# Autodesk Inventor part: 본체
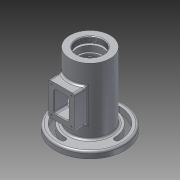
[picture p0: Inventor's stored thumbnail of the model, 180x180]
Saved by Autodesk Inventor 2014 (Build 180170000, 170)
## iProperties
Created: 2017-05
Part Number: 본체
Material: 알루미늄 6061
Document SubType Name: Modeling
Designer: Administrator
Density: 2.71 g/cm^3
Appearance: 알루미늄 - 평지
Mass: 682.498 g
Surface Area: 619.124 cm^2
Volume: 251.844 cm^3
Author: Administrator
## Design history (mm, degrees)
sketch "스케치1"
  geometry: C1 r 53 at (0, 0); 1 further point
  constraints: 1 centre point, 1 coincident
  dimensions: "d0" = 106 diameter of C1
extrude "돌출1" new body sketch "스케치1" distance "d1" = 10; taper "d2" = 0 deg
sketch "스케치2"
  geometry: C1 r 53 at (0, 0) reference; C2 r 31 at (0, 0)
  constraints: 1 centre point, 1 coincident
  dimensions: "d3" = 62 diameter of C2
extrude "돌출2" join sketch "스케치2" distance "d4" = 102; taper "d5" = 0 deg
sketch "스케치3"
  geometry: C1 r 53 at (0, 0) reference; C2 r 31 at (0, 0)
  constraints: 1 centre point, 1 coincident
  dimensions: "d6" = 62 diameter of C2
extrude "돌출3" join sketch "스케치3" distance "d7" = 3; taper "d8" = 0 deg
node "작업 평면1"
hole "구멍1" diameter "d12" = 40.376; stored, may be unused: countersink angle "d16" = 90 deg, drill point angle "d18" = 0 deg; dims "d10" = 10, "d11" = 10, "d13" = 6, "d14" = 4, "d15" = 2, "d17" = 9
sketch "스케치5"
  geometry: C1 r 20.188 at (0, 0) reference; C2 r 24 at (0, 0)
  constraints: 1 centre point, 1 coincident
  dimensions: "d19" = 48 diameter of C2
extrude "돌출4" cut sketch "스케치5" distance "d20" = 3; taper "d21" = 0 deg
sketch "스케치6"
  geometry: C1 r 24 at (0, 0) reference; C2 r 20 at (0, 0)
  constraints: 1 centre point, 1 coincident
  dimensions: "d22" = 40 diameter of C2
extrude "돌출5" cut sketch "스케치6" distance "d23" = 9; taper "d24" = 0 deg
sketch "스케치7"
  geometry: C1 r 20 at (0, 0) reference; C2 r 17.5 at (0, 0)
  constraints: 1 centre point, 1 coincident
  dimensions: "d25" = 35 diameter of C2
extrude "돌출6" cut sketch "스케치7" distance "d26" = 3.25; taper "d27" = 0 deg
sketch "스케치8"
  geometry: C1 r 17.5 at (0, 0) reference; C2 r 18.5 at (0, 0)
  constraints: 1 centre point, 1 coincident
  dimensions: "d28" = 37 diameter of C2
extrude "돌출7" cut sketch "스케치8" distance "d29" = 1.75; taper "d30" = 0 deg
sketch "스케치9"
  geometry: C1 r 18.5 at (0, 0) reference; C2 r 17.5 at (0, 0)
  constraints: 1 centre point, 1 coincident
  dimensions: "d31" = 35 diameter of C2
extrude "돌출8" cut sketch "스케치9" distance "d32" = 11; taper "d33" = 0 deg
sketch "스케치10"
  geometry: C1 r 17.5 at (0, 0) reference; C2 r 26 at (0, 0)
  constraints: 1 centre point, 1 coincident
  dimensions: "d34" = 52 diameter of C2
extrude "돌출9" cut sketch "스케치10" distance "d35" = 38; taper "d36" = 0 deg
sketch "스케치11"
  geometry: C1 r 26 at (0, 0) reference; C2 r 17.5 at (0, 0)
  constraints: 1 centre point, 1 coincident
  dimensions: "d37" = 35 diameter of C2
extrude "돌출10" cut sketch "스케치11" distance "d38" = 11; taper "d39" = 0 deg
sketch "스케치12"
  geometry: C1 r 17.5 at (0, 0) reference; C2 r 16.5 at (0, 0)
  constraints: 1 centre point, 1 coincident
  dimensions: "d40" = 33 diameter of C2
extrude "돌출11" cut sketch "스케치12" distance "d41" = 5; taper "d42" = 0 deg
sketch "스케치13"
  geometry: C1 r 16.5 at (0, 0) reference; C2 r 10 at (0, 0)
  constraints: 1 centre point, 1 coincident
  dimensions: "d43" = 20 diameter of C2
extrude "돌출12" cut sketch "스케치13" distance "d44" = 2.7; taper "d45" = 0 deg
sketch "스케치14"
  geometry: C1 r 10 at (0, 0) reference; C2 r 12.5 at (0, 0)
  constraints: 1 centre point, 1 coincident
  dimensions: "d46" = 25 diameter of C2
extrude "돌출13" cut sketch "스케치14" distance "d47" = 6.6; taper "d48" = 0 deg
sketch "스케치15"
  geometry: C1 r 12.5 at (0, 0) reference; C2 r 12.5 at (0, 0)
  constraints: 1 centre point, 1 coincident
  dimensions: "d49" = 25 diameter of C2
extrude "돌출14" cut sketch "스케치15" distance "d50" = 0.7; taper "d51" = 30 deg
node "작업 평면2"
node "작업 평면3"
sketch "스케치17"
  geometry: L1 (53, 10)-(53, 0) reference; L2 (53, 0)-(31, 0) reference; L3 (31, 0)-(31, -3) reference; L4 (31, -3)-(-31, -3) reference; L5 (-31, -3)-(-31, 0) reference; L6 (-31, 0)-(-53, 0) reference; L7 (-53, 0)-(-53, 10) reference; L8 (-53, 10)-(-31, 10) reference; L9 (-31, 10)-(-31, 112) reference; L10 (-31, 112)-(-20.188, 112) reference; L11 (-20.188, 112)-(-20.188, 103) reference; L12 (-20.188, 103)-(-24, 103) reference; L13 (-24, 103)-(-24, 100) reference; L14 (-24, 100)-(-20, 100) reference; L15 (-20, 100)-(-20, 91) reference; L16 (-20, 91)-(-17.5, 91) reference; L17 (-17.5, 91)-(-17.5, 87.75) reference; L18 (-17.5, 87.75)-(-18.5, 87.75) reference; L19 (-18.5, 87.75)-(-18.5, 86) reference; L20 (-18.5, 86)-(-17.5, 86) reference; L21 (-17.5, 86)-(-17.5, 75) reference; L22 (-17.5, 75)-(-26, 75) reference; L23 (-26, 75)-(-26, 37) reference; L24 (-26, 37)-(-17.5, 37) reference; L25 (-17.5, 37)-(-17.5, 26) reference; L26 (-17.5, 26)-(-16.5, 26) reference; L27 (-16.5, 26)-(-16.5, 21) reference; L28 (-16.5, 21)-(-10, 21) reference; L29 (-10, 21)-(-10, 18.3) reference; L30 (-10, 18.3)-(-12.5, 18.3) reference; L31 (-12.5, 18.3)-(-12.5, 11.7) reference; L32 (-12.5, 11.7)-(-12.904, 11) reference; L33 (-12.904, 11)-(12.904, 11) reference; L34 (12.904, 11)-(12.5, 11.7) reference; L35 (12.5, 11.7)-(12.5, 18.3) reference; L36 (12.5, 18.3)-(10, 18.3) reference; L37 (10, 18.3)-(10, 21) reference; L38 (10, 21)-(16.5, 21) reference; L39 (16.5, 21)-(16.5, 26) reference; L40 (16.5, 26)-(17.5, 26) reference; L41 (17.5, 26)-(17.5, 37) reference; L42 (17.5, 37)-(26, 37) reference; L43 (26, 37)-(26, 75) reference; L44 (26, 75)-(17.5, 75) reference; L45 (17.5, 75)-(17.5, 86) reference; L46 (17.5, 86)-(18.5, 86) reference; L47 (18.5, 86)-(18.5, 87.75) reference; L48 (18.5, 87.75)-(17.5, 87.75) reference; L49 (17.5, 87.75)-(17.5, 91) reference; L50 (17.5, 91)-(20, 91) reference; L51 (20, 91)-(20, 100) reference; L52 (20, 100)-(24, 100) reference; L53 (24, 100)-(24, 103) reference; L54 (24, 103)-(20.188, 103) reference; L55 (20.188, 103)-(20.188, 112) reference; L56 (20.188, 112)-(31, 112) reference; L57 (31, 112)-(31, 10) reference; L58 (31, 10)-(53, 10) reference; L59 (0, 11)-(0, -3); L60 (0, 11)-(16, 11); L61 (0, -3)-(22, -3); L62 (16, 11)-(22, -3); 1 further point
  constraints: 8 end point, 2 midpoint, 2 point on line
  dimensions: "d54" = 44 diameter of L61.end L59; "d55" = 32 diameter of L60.end L59
revolve "회전1" sketch "스케치17" stored, may be unused: angle "d56" = 90 deg
node "작업 평면4"
node "작업 평면5"
sketch "스케치19"
  geometry: L1 (-29.547, 0)-(-29.547, 10) reference; L2 (-29.547, 10)-(29.547, 10) reference; L3 (29.547, 10)-(29.547, 0) reference; L4 (29.547, 0)-(-29.547, 0) reference; L5 (31, 112)-(-31, 112) reference; L6 (20, 81)-(-20, 81); L7 (-20, 81)-(-20, 31); L8 (-20, 31)-(20, 31); L9 (20, 31)-(20, 81); L10 (20, 81)-(-20, 31); L11 (-20, 81)-(20, 31); 4 further points
  constraints: 12 end point, 4 midpoint, 2 parallel, 1 horizontal, 1 perpendicular, 1 vertical alignment
  dimensions: "d62" = 56 distance from line of L5 point (0, 56); "d63" = 50 distance of L8.end L6.start; "d64" = 40 distance of L6.start L6.end
extrude "돌출15" join sketch "스케치19" stored distance "d65" = 0.7; taper "d66" = 0 deg
sketch "스케치20"
  geometry: L1 (-20, 81)-(-20, 31) reference; L2 (-20, 31)-(20, 31) reference; L3 (20, 31)-(20, 81) reference; L4 (20, 81)-(-20, 81) reference; L5 (11, 72)-(11, 40); L6 (11, 40)-(-11, 40); L7 (-11, 40)-(-11, 72); L8 (-11, 72)-(11, 72); 3 further points
  constraints: 8 end point, 2 midpoint, 1 vertical alignment, 3 other
  dimensions: "d68" = 32 distance of L5.start L5.end; "d69" = 22 distance of L7.end L5.start (derived)
extrude "돌출16" cut sketch "스케치20" stored distance "d70" = 0.7; taper "d71" = 0 deg
hole "구멍2" diameter "d74" = 2.459; stored, may be unused: countersink angle "d78" = 90 deg, drill point angle "d80" = 118 deg; dims "d72" = 4.5, "d73" = 4.5, "d75" = 6, "d76" = 4, "d77" = 2, "d79" = 8
sketch "스케치22"
  geometry: C1 r 31 at (0, 0) reference; C2 r 53 at (0, 0) reference; A1 r 41.5 centre (0, 0) between (41.5, 0) and (0, -41.5); A2 r 37.5 centre (0, 0) between (37.5, 0) and (0, 37.5); A3 r 4 centre (41.5, 0) between (45.5, 0) and (37.5, 0); A4 r 4 centre (0, -41.5) between (0, -37.5) and (0, -45.5); A5 r 4 centre (0, 41.5) between (0, 37.5) and (0, 45.5); A6 r 4 centre (-41.5, 0) between (-45.5, 0) and (-37.5, 0); A7 r 45.5 centre (0, 0) between (0, 45.5) and (-45.5, 0); A8 r 37.5 centre (0, 0) between (0, 37.5) and (-37.5, 0); A9 r 37.5 centre (0, 0) between (0, -37.5) and (37.5, 0); A10 r 45.5 centre (0, 0) between (0, -45.5) and (45.5, 0)
  constraints: 22 point on circle, 10 centre point, 6 coincident, 2 horizontal alignment, 2 vertical alignment, 1 tangent
  dimensions: "d87" = 83 diameter of A1; "d88" = 75 diameter of A2; "d89" = 8 diameter of A3; "d90" = 8 diameter of A4; "d91" = 8 diameter of A5; "d92" = 8 diameter of A6; "d93" = 45.5 radius of A7
extrude "돌출17" cut sketch "스케치22" distance "d94" = 10; taper "d95" = 0 deg
node "작업 평면6"
sketch "스케치23"
  geometry: L1 (-16.613, 37)-(16.613, 37) reference; L2 (16.613, 37)-(16.613, 75) reference; L3 (16.613, 75)-(-16.613, 75) reference; L4 (-16.613, 75)-(-16.613, 37) reference; L5 (49.082, 10)-(49.082, 0) reference; L6 (49.082, 0)-(40.869, 0) reference; L7 (40.869, 0)-(40.869, 10) reference; L8 (40.869, 10)-(49.082, 10) reference; L9 (-49.082, 0)-(-49.082, 10) reference; L10 (-49.082, 10)-(-23.685, 10) reference; L11 (-23.685, 10)-(-23.685, 112) reference; L12 (-23.685, 112)-(-2.749, 112) reference; L13 (-2.749, 112)-(-2.749, 103) reference; L14 (-2.749, 103)-(-13.266, 103) reference; L15 (-13.266, 103)-(-13.266, 100) reference; L16 (-13.266, 100)-(0, 100) reference; L17 (0, 91)-(0, 100) reference; L18 (-23.685, 0)-(-49.082, 0) reference; L19 (-23.685, -3)-(-23.685, 0) reference; L20 (-9.165, -3)-(-23.685, -3) reference; L21 (23.685, -3)-(9.165, -3) reference; L22 (23.685, 0)-(23.685, -3) reference; L23 (31.721, 0)-(23.685, 0) reference; L24 (31.721, 10)-(31.721, 0) reference; L25 (23.685, 10)-(31.721, 10) reference; L26 (23.685, 31)-(23.685, 10) reference; L27 (44, 31)-(23.685, 31) reference; L28 (44, 81)-(44, 31) reference; L29 (23.685, 81)-(44, 81) reference; L30 (23.685, 112)-(23.685, 81) reference; L31 (2.749, 112)-(23.685, 112) reference; L32 (2.749, 103)-(2.749, 112) reference; L33 (13.266, 103)-(2.749, 103) reference; L34 (13.266, 100)-(13.266, 103) reference; L35 (0, 100)-(13.266, 100) reference; L36 (23.685, 81)-(23.685, 31) reference; 2 further points
  constraints: 1 horizontal alignment, 1 other
  dimensions: "d97" = 56 distance from line of L31 point (36, 56); "d98" = 8 distance from line of point (36, 56) L28
feature "엠보싱1" sketch "스케치23" dims "d99" = 0.5, "d100" = 0
fillet "모깎기1" dims "d101" = 3
fillet "모깎기2" dims "d102" = 0.3
fillet "모깎기3" dims "d103" = 3
fillet "모깎기4" dims "d104" = 3
fillet "모깎기5" dims "d105" = 3
fillet "모깎기6" dims "d106" = 3
chamfer "모따기1" distance "d107" = 1; stored, may be unused: second distance "d108" = 2, angle "d109" = 45 deg
fillet "모깎기7" dims "d113" = 3
fillet "모깎기9" dims "d115" = 3
fillet "모깎기10" dims "d116" = 3
chamfer "모따기3" distance "d117" = 1; stored, may be unused: second distance "d118" = 2, angle "d119" = 45 deg
fillet "모깎기11" dims "d120" = 0.3
node "솔리드1"
pattern_linear "직사각형 패턴1" dims "d83" = 41, "d86" = 31
node "절단 모서리 투영3"
node "절단 모서리 투영5"
node "절단 모서리 투영6"
other parameters: "d9" = 0, "d52" = 0, "d53" = 0, "d57" = -31, "d61" = -44
